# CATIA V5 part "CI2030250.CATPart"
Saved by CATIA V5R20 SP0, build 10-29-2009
Part number: CI2030250
Bounding box of the stored display mesh (mm): x -29 to 29, y -24.37 to 295, z -40.082 to 32.547
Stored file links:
  C:\Users\Raffaele\Desktop\3D X SITO CF\BOLEX\19-INCLINED ASSEMBLY REF_CI\CI2030250.CATPart
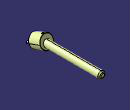
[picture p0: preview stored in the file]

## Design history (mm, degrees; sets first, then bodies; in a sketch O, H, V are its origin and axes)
Set1
  DatumSurface1 to DatumSurface16 "MANIFOLD_SOLID_BREP #399"
  DatumSurface17 to DatumSurface39 "MANIFOLD_SOLID_BREP #1148"
Body1 (main body)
